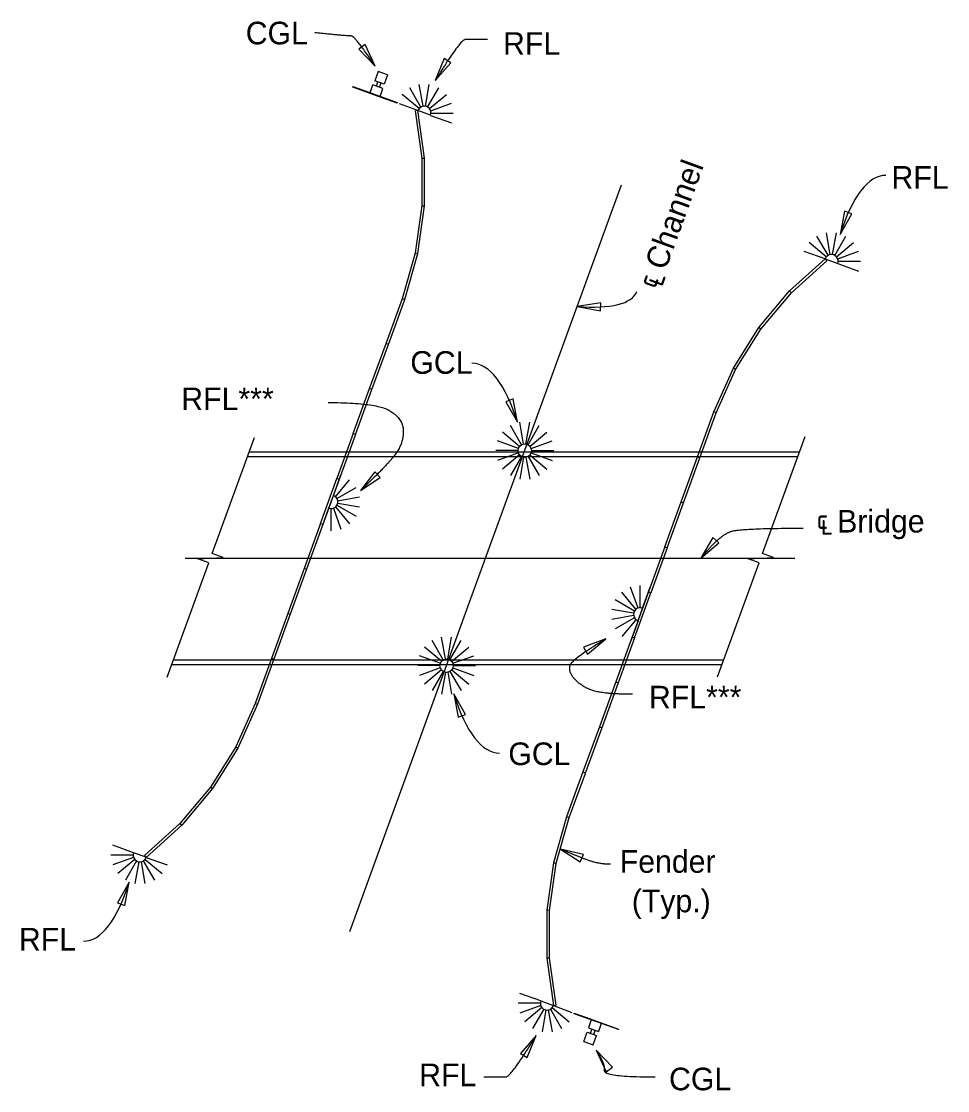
# Model space of a CAD drawing. Extents: x 84082 to 86787, y 72619 to 74101.
# Drawn here: x 84138.4 to 84448, y 73710.8 to 74068.1 of the extents above; entities that cross this region are included whole.
import ezdxf

# ---------------------------------------------------------------- set-up
doc = ezdxf.new("R2010")
doc.units = 0
for name, color, linetype in [('Dimension', 7, 'Continuous'), ('Miscellaneous', 7, 'Continuous'), ('NavLight', 7, 'Continuous'), ('SupstrConc', 7, 'Continuous'), ('TextStructures', 7, 'Continuous'), ('Wood', 7, 'Continuous')]:
    doc.layers.add(name, color=color, linetype=linetype)

msp = doc.modelspace()

# ---------------------------------------------------------------- linework, layer by layer
at = {"layer": 'Dimension'}
for points in [[(84256.72, 74053.21), (84253.37, 74060.38), (84251.19, 74058.88)], [(84276.78, 74048.32), (84281.97, 74054.31), (84279.71, 74055.68)], [(84412.08, 73996.91), (84416.01, 74003.79), (84413.52, 74004.7)], [(84324.24, 73972.88), (84332.02, 73971.4), (84332.07, 73974.05)], [(84304.27, 73934.16), (84302.79, 73941.94), (84300.31, 73941.02)], [(84251.75, 73911.33), (84258.35, 73915.72), (84256.54, 73917.64)], [(84365.53, 73888.76), (84371.55, 73893.91), (84369.52, 73895.6)], [(84333.77, 73861.76), (84326.35, 73858.97), (84327.69, 73856.69)], [(84282.98, 73843.36), (84284.45, 73835.57), (84286.93, 73836.49)], [(84318.59, 73791.54), (84325.25, 73787.25), (84326.29, 73789.68)], [(84174.49, 73780.48), (84170.56, 73773.6), (84173.05, 73772.69)], [(84310.46, 73729.19), (84305.27, 73723.21), (84307.54, 73721.83)], [(84330.52, 73724.31), (84333.88, 73717.14), (84336.06, 73718.64)]]:
    msp.add_lwpolyline(points, close=True, dxfattribs=at)
for points in [[(84187.19, 73848.95), (84201.1, 73887.17), (84197.46, 73888.5), (84201.68, 73888.76), (84205.9, 73889.02), (84202.26, 73890.34), (84216.34, 73929.03)], [(84371.13, 73849.09), (84384.99, 73887.17), (84381.35, 73888.5), (84385.56, 73888.76), (84389.78, 73889.02), (84386.14, 73890.34), (84400.37, 73929.44)]]:
    msp.add_lwpolyline(points, dxfattribs=at)
for centre, major_axis, ratio, start_param, end_param in [((84426.42, 73959.37), (-0.91, -57.27), 0.343516, 3.141594, 4.002916), ((84279.16, 74003.89), (-65, 26.05), 0.265294, 2.43766, 3.141592), ((84289.93, 73896.62), (0.91, -57.27), 0.343516, 2.28027, 3.141592), ((84297.31, 73880.9), (-0.91, 57.27), 0.343516, 2.28027, 3.141592), ((84160.16, 73818.02), (0.91, 57.27), 0.343516, 3.141594, 4.002916)]:
    msp.add_ellipse(centre, major_axis=major_axis, ratio=ratio, start_param=start_param, end_param=end_param, dxfattribs=at)
for points in [[(84256.72, 74053.21), (84249.89, 74063.29), (84247.53, 74063.2), (84236.54, 74064.33)], [(84294.23, 74062.1), (84288.47, 74062.1), (84285.16, 74062.1), (84276.78, 74048.32)], [(84240.93, 73940.75), (84257.1, 73940.75), (84266.1, 73935.28), (84266.1, 73926.77), (84259.9, 73918.99), (84251.75, 73911.33)], [(84365.53, 73888.76), (84372.06, 73896.73), (84379.63, 73898.77), (84399.7, 73898.77)], [(84342.66, 73843.27), (84334.29, 73843.27), (84326.61, 73845.19), (84321.29, 73850.34), (84322.25, 73855.05), (84333.77, 73861.76)], [(84335.33, 73786.45), (84331.93, 73786.45), (84325.72, 73788.49), (84318.59, 73791.54)], [(84293.02, 73715.41), (84298.77, 73715.41), (84302.09, 73715.41), (84310.46, 73729.19)], [(84330.52, 73724.31), (84333.66, 73719.77), (84332.79, 73715.41), (84350.24, 73715.41)]]:
    msp.add_open_spline(points, degree=2, dxfattribs=at)
at = {"layer": 'Miscellaneous'}
for p, q in [((84293.62, 73888.76), (84339.03, 74013.52)), ((84193.16, 73888.76), (84293.62, 73888.76)), ((84248.21, 73763.99), (84293.62, 73888.76)), ((84293.62, 73888.76), (84396.93, 73888.76))]:
    msp.add_line(p, q, dxfattribs=at)
at = {"layer": 'NavLight'}
for p, q in [((84257.68, 74051.37), (84256.58, 74048.31)), ((84260.77, 74050.27), (84257.68, 74051.37)), ((84260.77, 74050.27), (84259.67, 74047.2)), ((84254.98, 74044.27), (84255.93, 74046.92)), ((84259.28, 74045.71), (84255.93, 74046.92)), ((84259.67, 74047.2), (84256.58, 74048.31)), ((84257.08, 74046.5), (84257.59, 74047.94)), ((84258.14, 74046.12), (84258.65, 74047.56)), ((84258.33, 74043.07), (84259.28, 74045.71)), ((84271.96, 74039.48), (84268.26, 74045.89)), ((84272.7, 74039.74), (84271.41, 74047.03)), ((84273.48, 74039.74), (84274.77, 74047.03)), ((84274.21, 74039.48), (84277.92, 74045.89)), ((84271.37, 74038.97), (84265.7, 74043.73)), ((84274.81, 74038.97), (84280.48, 74043.73)), ((84270.98, 74038.3), (84264.8, 74040.54)), ((84275.2, 74036.74), (84270.98, 74038.3)), ((84275.24, 74038.29), (84282.2, 74040.82)), ((84275.23, 74036.73), (84282.18, 74034.2)), ((84275.37, 74037.51), (84282.77, 74037.51)), ((84408.05, 73989.95), (84404.35, 73996.36)), ((84408.82, 73990.2), (84407.53, 73997.49)), ((84409.6, 73990.2), (84410.88, 73997.49)), ((84410.33, 73989.93), (84414.03, 73996.34)), ((84407.45, 73989.44), (84401.78, 73994.2)), ((84410.93, 73989.43), (84416.6, 73994.19)), ((84407.06, 73988.75), (84400.1, 73991.28)), ((84407.09, 73988.74), (84411.32, 73987.21)), ((84411.32, 73988.75), (84418.28, 73991.29)), ((84411.32, 73987.21), (84418.28, 73984.68)), ((84411.46, 73987.98), (84418.86, 73987.98)), ((84304.97, 73926.12), (84299.3, 73930.88)), ((84305.57, 73926.62), (84301.87, 73933.03)), ((84306.3, 73926.89), (84305.02, 73934.18)), ((84307.09, 73926.89), (84308.37, 73934.18)), ((84307.82, 73926.62), (84311.52, 73933.03)), ((84308.45, 73926.13), (84314.12, 73930.89)), ((84304.58, 73925.44), (84297.62, 73927.98)), ((84308.85, 73925.44), (84315.8, 73927.97)), ((84304.44, 73924.68), (84297.04, 73924.68)), ((84304.58, 73923.91), (84297.62, 73921.37)), ((84308.85, 73923.91), (84315.8, 73921.38)), ((84308.98, 73924.69), (84316.38, 73924.69)), ((84304.97, 73923.23), (84299.3, 73918.47)), ((84305.57, 73922.73), (84301.87, 73916.32)), ((84306.3, 73922.46), (84305.02, 73915.17)), ((84307.09, 73922.46), (84308.37, 73915.17)), ((84307.82, 73922.73), (84311.52, 73916.32)), ((84308.45, 73923.22), (84314.12, 73918.46)), ((84242.71, 73909.68), (84245.24, 73916.64)), ((84243.39, 73909.29), (84248.14, 73914.96)), ((84241.16, 73905.46), (84242.71, 73909.68)), ((84243.89, 73908.69), (84250.3, 73912.4)), ((84243.39, 73905.85), (84248.14, 73900.18)), ((84243.89, 73906.44), (84250.3, 73902.74)), ((84244.16, 73907.96), (84251.45, 73909.25)), ((84244.16, 73907.18), (84251.45, 73905.89)), ((84241.14, 73905.43), (84238.61, 73898.47)), ((84241.92, 73905.29), (84241.92, 73897.89)), ((84242.71, 73905.42), (84245.24, 73898.46)), ((84343.86, 73871.67), (84339.1, 73877.34)), ((84344.54, 73872.06), (84342, 73879.02)), ((84345.31, 73872.2), (84345.31, 73879.6)), ((84346.08, 73872.06), (84348.61, 73879.02)), ((84343.36, 73871.07), (84336.95, 73874.77)), ((84343.09, 73870.34), (84335.8, 73871.62)), ((84344.55, 73867.83), (84346.08, 73872.06)), ((84343.09, 73869.56), (84335.8, 73868.27)), ((84343.34, 73868.79), (84336.93, 73865.09)), ((84343.85, 73868.19), (84339.09, 73862.52)), ((84344.54, 73867.8), (84342.01, 73860.84)), ((84279.42, 73854.79), (84275.72, 73861.2)), ((84280.16, 73855.06), (84278.87, 73862.35)), ((84280.94, 73855.06), (84282.23, 73862.35)), ((84281.68, 73854.79), (84285.38, 73861.2)), ((84278.44, 73853.61), (84271.48, 73856.14)), ((84278.83, 73854.29), (84273.16, 73859.05)), ((84282.31, 73854.3), (84287.98, 73859.06)), ((84282.7, 73853.61), (84289.66, 73856.14)), ((84278.3, 73852.84), (84270.9, 73852.84)), ((84282.83, 73852.86), (84290.23, 73852.86)), ((84278.44, 73852.07), (84271.48, 73849.54)), ((84278.83, 73851.4), (84273.16, 73846.64)), ((84279.42, 73850.89), (84275.72, 73844.48)), ((84280.16, 73850.63), (84278.87, 73843.34)), ((84280.94, 73850.63), (84282.23, 73843.34)), ((84281.68, 73850.89), (84285.38, 73844.48)), ((84282.31, 73851.39), (84287.98, 73846.63)), ((84282.7, 73852.08), (84289.66, 73849.54)), ((84175.92, 73790.3), (84168.97, 73792.83)), ((84175.79, 73789.53), (84168.39, 73789.53)), ((84175.92, 73788.76), (84168.97, 73786.23)), ((84176.31, 73788.09), (84170.64, 73783.33)), ((84180.16, 73788.78), (84175.92, 73790.3)), ((84179.8, 73788.08), (84185.47, 73783.32)), ((84180.19, 73788.77), (84187.14, 73786.24)), ((84176.91, 73787.58), (84173.21, 73781.17)), ((84177.65, 73787.32), (84176.36, 73780.03)), ((84178.43, 73787.32), (84179.71, 73780.03)), ((84179.19, 73787.56), (84182.89, 73781.15)), ((84312.02, 73740.79), (84305.06, 73743.32)), ((84311.87, 73740.01), (84304.47, 73740.01)), ((84312.01, 73739.22), (84305.05, 73736.69)), ((84312.43, 73738.54), (84306.76, 73733.79)), ((84313.03, 73738.04), (84309.33, 73731.63)), ((84312.05, 73740.77), (84316.27, 73739.22)), ((84315.28, 73738.04), (84318.98, 73731.63)), ((84315.88, 73738.54), (84321.55, 73733.79)), ((84316.27, 73739.22), (84322.44, 73736.97)), ((84313.76, 73737.77), (84312.48, 73730.48)), ((84314.55, 73737.77), (84315.83, 73730.48)), ((84328.91, 73734.45), (84327.96, 73731.8)), ((84327.96, 73731.8), (84331.32, 73730.6)), ((84329.11, 73731.39), (84328.59, 73729.95)), ((84330.17, 73731.01), (84329.65, 73729.58)), ((84332.27, 73733.25), (84331.32, 73730.6)), ((84326.48, 73727.25), (84327.58, 73730.32)), ((84326.48, 73727.25), (84329.57, 73726.14)), ((84327.58, 73730.32), (84330.67, 73729.21)), ((84329.57, 73726.14), (84330.67, 73729.21))]:
    msp.add_line(p, q, dxfattribs=at)
for centre in [(84306.7, 73924.68), (84280.55, 73852.84)]:
    msp.add_circle(centre, 2.25, dxfattribs=at)
for centre, start, end in [((84273.09, 74037.53), 339.6086, 160), ((84409.21, 73987.98), 340, 160.3914), ((84241.94, 73907.57), 249.6086, 70), ((84345.31, 73869.95), 70, 250.3914), ((84178.04, 73789.53), 160, 340.3914), ((84314.16, 73739.99), 159.6086, 340)]:
    msp.add_arc(centre, 2.25, start, end, dxfattribs=at)
at = {"layer": 'SupstrConc'}
for p, q in [((84214.62, 73924.3), (84398.5, 73924.3)), ((84214.06, 73922.76), (84397.94, 73922.76)), ((84188.74, 73853.22), (84372.63, 73853.22)), ((84189.31, 73854.76), (84373.19, 73854.76))]:
    msp.add_line(p, q, dxfattribs=at)
at = {"layer": 'Wood'}
for p, q in [((84270.98, 74038.3), (84270.15, 74038.18)), ((84272.37, 74022.39), (84270.15, 74038.18)), ((84273.2, 74022.45), (84270.98, 74038.3)), ((84272.37, 74022.39), (84273.2, 74022.45)), ((84272.37, 74006.51), (84272.37, 74022.39)), ((84273.2, 74006.45), (84273.2, 74022.45)), ((84270.16, 73990.78), (84272.37, 74006.51)), ((84270.98, 73990.61), (84273.2, 74006.45)), ((84272.37, 74006.51), (84273.2, 74006.45)), ((84265.77, 73975.49), (84270.16, 73990.78)), ((84266.56, 73975.23), (84270.98, 73990.61)), ((84270.16, 73990.78), (84270.98, 73990.61)), ((84395.2, 73978.05), (84407.09, 73988.75)), ((84395.8, 73977.47), (84407.65, 73988.13)), ((84407.09, 73988.75), (84407.65, 73988.13)), ((84384.92, 73965.79), (84395.2, 73978.05)), ((84385.59, 73965.3), (84395.8, 73977.47)), ((84395.8, 73977.47), (84395.2, 73978.05)), ((84260.31, 73960.48), (84265.77, 73975.49)), ((84261.09, 73960.19), (84266.56, 73975.23)), ((84265.77, 73975.49), (84266.56, 73975.23)), ((84376.44, 73952.22), (84384.92, 73965.79)), ((84377.18, 73951.83), (84385.59, 73965.3)), ((84385.59, 73965.3), (84384.92, 73965.79)), ((84254.84, 73945.44), (84260.31, 73960.48)), ((84255.62, 73945.16), (84261.09, 73960.19)), ((84261.09, 73960.19), (84260.31, 73960.48)), ((84369.93, 73937.61), (84376.44, 73952.22)), ((84370.7, 73937.29), (84377.18, 73951.83)), ((84377.18, 73951.83), (84376.44, 73952.22)), ((84249.36, 73930.41), (84254.84, 73945.44)), ((84250.15, 73930.12), (84255.62, 73945.16)), ((84255.62, 73945.16), (84254.84, 73945.44)), ((84364.46, 73922.57), (84369.93, 73937.61)), ((84365.24, 73922.29), (84370.7, 73937.29)), ((84370.7, 73937.29), (84369.93, 73937.61)), ((84249.36, 73930.41), (84243.89, 73915.37)), ((84250.15, 73930.12), (84244.68, 73915.09)), ((84250.15, 73930.12), (84249.36, 73930.41)), ((84358.99, 73907.54), (84364.46, 73922.57)), ((84359.77, 73907.25), (84365.24, 73922.29)), ((84364.46, 73922.57), (84365.24, 73922.29)), ((84238.42, 73900.34), (84243.89, 73915.37)), ((84244.68, 73915.09), (84239.2, 73900.05)), ((84244.68, 73915.09), (84243.89, 73915.37)), ((84353.51, 73892.5), (84358.99, 73907.54)), ((84354.3, 73892.22), (84359.77, 73907.25)), ((84358.99, 73907.54), (84359.77, 73907.25)), ((84238.42, 73900.34), (84232.95, 73885.3)), ((84239.2, 73900.05), (84233.73, 73885.02)), ((84239.2, 73900.05), (84238.42, 73900.34)), ((84353.51, 73892.5), (84348.04, 73877.47)), ((84354.3, 73892.22), (84348.82, 73877.18)), ((84353.51, 73892.5), (84354.3, 73892.22)), ((84232.95, 73885.3), (84227.48, 73870.29)), ((84233.73, 73885.02), (84228.26, 73869.98)), ((84233.73, 73885.02), (84232.95, 73885.3)), ((84348.04, 73877.47), (84342.57, 73862.43)), ((84348.04, 73877.47), (84348.82, 73877.18)), ((84343.35, 73862.14), (84348.82, 73877.18)), ((84227.48, 73870.27), (84222.01, 73855.26)), ((84228.26, 73869.98), (84227.48, 73870.27)), ((84228.26, 73869.98), (84222.79, 73854.95)), ((84342.57, 73862.43), (84337.1, 73847.39)), ((84343.35, 73862.14), (84337.88, 73847.11)), ((84342.57, 73862.43), (84343.35, 73862.14)), ((84222, 73855.23), (84216.54, 73840.22)), ((84222.79, 73854.95), (84217.31, 73839.91)), ((84222.79, 73854.95), (84222, 73855.23)), ((84337.1, 73847.39), (84331.62, 73832.36)), ((84337.88, 73847.11), (84332.42, 73832.1)), ((84337.1, 73847.39), (84337.88, 73847.11)), ((84216.54, 73840.22), (84210.07, 73825.69)), ((84217.31, 73839.91), (84210.81, 73825.3)), ((84216.54, 73840.22), (84217.31, 73839.91)), ((84331.62, 73832.36), (84326.15, 73817.32)), ((84332.41, 73832.07), (84326.94, 73817.07)), ((84331.62, 73832.36), (84332.41, 73832.07)), ((84210.07, 73825.69), (84201.65, 73812.22)), ((84210.81, 73825.3), (84202.33, 73811.73)), ((84210.07, 73825.69), (84210.81, 73825.3)), ((84326.15, 73817.32), (84320.68, 73802.29)), ((84326.94, 73817.04), (84321.47, 73802.03)), ((84326.15, 73817.32), (84326.94, 73817.04)), ((84201.65, 73812.22), (84191.44, 73800.05)), ((84202.33, 73811.73), (84192.04, 73799.47)), ((84201.65, 73812.22), (84202.33, 73811.73)), ((84320.68, 73802.29), (84316.27, 73786.91)), ((84321.47, 73802.03), (84320.68, 73802.29)), ((84191.44, 73800.05), (84179.6, 73789.38)), ((84192.04, 73799.47), (84180.15, 73788.76)), ((84191.44, 73800.05), (84192.04, 73799.47)), ((84321.47, 73802.03), (84317.09, 73786.74)), ((84180.15, 73788.76), (84179.6, 73789.38)), ((84316.27, 73786.91), (84314.04, 73771.07)), ((84317.09, 73786.74), (84314.88, 73771.01)), ((84317.09, 73786.74), (84316.27, 73786.91)), ((84314.04, 73771.07), (84314.04, 73755.07)), ((84314.88, 73771.01), (84314.04, 73771.07)), ((84314.88, 73771.01), (84314.88, 73755.12)), ((84314.88, 73755.12), (84314.04, 73755.07)), ((84314.04, 73755.07), (84316.27, 73739.22)), ((84314.88, 73755.12), (84317.1, 73739.34)), ((84316.27, 73739.22), (84317.1, 73739.34))]:
    msp.add_line(p, q, dxfattribs=at)
for points in [[(84258.71, 74042.73), (84249.18, 74046.15), (84249.24, 74046.33), (84254.54, 74044.43)], [(84254.54, 74044.43), (84264.07, 74041.01), (84264.01, 74040.83), (84258.71, 74042.73)], [(84332.71, 73733.09), (84323.18, 73736.51), (84323.24, 73736.68), (84328.53, 73734.79)], [(84328.53, 73734.79), (84338.06, 73731.37), (84338, 73731.19), (84332.71, 73733.09)]]:
    msp.add_lwpolyline(points, dxfattribs=at)

# ---------------------------------------------------------------- texts
at = {"layer": 'Dimension'}
for s, p in [('Fender', (84338.44, 73783.62)), ('(Typ.)', (84342.46, 73770.42))]:
    msp.add_text(s, height=7.56, dxfattribs=at).set_placement(p)
at = {"layer": 'TextStructures'}
for s, p in [('CGL', (84213.42, 74060.45)), ('RFL', (84299.43, 74056.96)), ('RFL', (84429.27, 74012.22)), ('GCL', (84268.44, 73950.36)), ('RFL***', (84191.87, 73938.21)), ('℄ Bridge ', (84404.2, 73897.32)), ('RFL***', (84348.2, 73838.53)), ('GCL', (84301.19, 73819.6)), ('RFL', (84137.61, 73757.61)), ('RFL', (84271.4, 73712.29)), ('CGL', (84354.91, 73710.93))]:
    msp.add_text(s, height=7.56, dxfattribs=at).set_placement(p)
msp.add_text('℄ Channel', height=7.56, rotation=70, dxfattribs=at).set_placement((84351.39, 73978.13))

doc.saveas('drawing.dxf')
